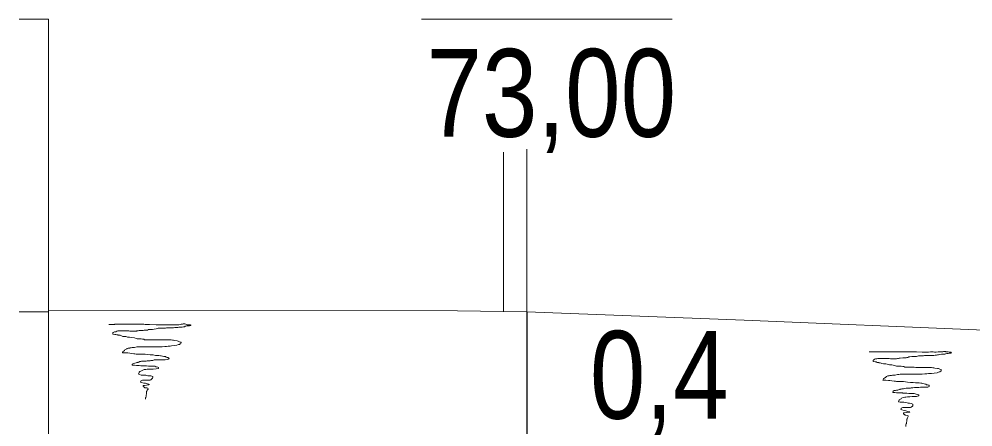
# Model space of a CAD drawing. Extents: x 640104 to 640970, y 6442278 to 6442689.
# Drawn here: x 640552.71 to 640585.31, y 6442645.01 to 6442658.94 of the extents above; entities that cross this region are included whole.
import ezdxf
from ezdxf.enums import TextEntityAlignment as Align

# ---------------------------------------------------------------- set-up
doc = ezdxf.new("R2010")
doc.units = 0
doc.header["$LTSCALE"] = 1.2
for name, color, linetype, lineweight in [('30', 7, 'Continuous', 13), ('31', 7, 'Continuous', 13), ('32', 7, 'Continuous', 25), ('35', 7, 'Continuous', 35), ('40', 7, 'Continuous', 13)]:
    doc.layers.add(name, color=color, linetype=linetype, lineweight=lineweight)

msp = doc.modelspace()

# ---------------------------------------------------------------- linework, layer by layer
at = {"layer": '30'}
for p, q in [((640552.71, 6442658.94), (640553.71, 6442658.94)), ((640553.71, 6442488.94), (640553.71, 6442658.94)), ((640552.71, 6442648.94), (640553.71, 6442648.94))]:
    msp.add_line(p, q, dxfattribs=at)
at = {"layer": '31'}
msp.add_lwpolyline([(640553.71, 6442649), (640567.7, 6442648.97), (640570.07, 6442648.94), (640577.49, 6442648.66), (640585.71, 6442648.31), (640594.63, 6442647.18), (640602.39, 6442645.28), (640608.86, 6442643.53), (640614.97, 6442642.09), (640621.18, 6442640.93)], dxfattribs=at)
at = {"layer": '32', "lineweight": 13}
msp.add_line((640566.46, 6442658.94), (640575.03, 6442658.94), dxfattribs=at)
at = {"layer": '32'}
msp.add_line((640570.07, 6442648.94), (640570.07, 6442558.94), dxfattribs=at)
at = {"layer": '35', "lineweight": 13}
for p, q in [((640569.27, 6442648.94), (640569.27, 6442654.4)), ((640570.07, 6442648.94), (640570.07, 6442654.5))]:
    msp.add_line(p, q, dxfattribs=at)
at = {"layer": '40'}
for points in [[(640555.78, 6442648.51), (640555.82, 6442648.51), (640555.89, 6442648.51), (640555.97, 6442648.51), (640555.98, 6442648.52), (640556.05, 6442648.52), (640556.16, 6442648.52), (640556.37, 6442648.52), (640556.49, 6442648.52), (640556.52, 6442648.52), (640556.54, 6442648.52), (640556.59, 6442648.52), (640556.65, 6442648.52), (640556.72, 6442648.52), (640556.77, 6442648.52), (640556.81, 6442648.52), (640556.87, 6442648.52), (640556.92, 6442648.52), (640556.97, 6442648.52), (640557.02, 6442648.51), (640557.05, 6442648.51), (640557.1, 6442648.51), (640557.17, 6442648.51), (640557.39, 6442648.5), (640557.6, 6442648.5), (640557.66, 6442648.5), (640557.7, 6442648.5), (640557.73, 6442648.5), (640557.76, 6442648.5), (640557.81, 6442648.5), (640557.87, 6442648.5), (640557.9, 6442648.5), (640557.93, 6442648.5), (640557.94, 6442648.5), (640557.97, 6442648.5), (640558.01, 6442648.5), (640558.04, 6442648.5), (640558.07, 6442648.5), (640558.13, 6442648.5), (640558.17, 6442648.5), (640558.22, 6442648.51), (640558.25, 6442648.52), (640558.29, 6442648.52), (640558.32, 6442648.53), (640558.35, 6442648.53), (640558.38, 6442648.53), (640558.41, 6442648.52), (640558.43, 6442648.51), (640558.46, 6442648.5), (640558.49, 6442648.5)], [(640558.49, 6442648.5), (640558.52, 6442648.5), (640558.54, 6442648.5), (640558.57, 6442648.5), (640558.59, 6442648.48), (640558.57, 6442648.47), (640558.58, 6442648.48), (640558.56, 6442648.47), (640558.53, 6442648.46), (640558.49, 6442648.46), (640558.46, 6442648.46), (640558.43, 6442648.46), (640558.41, 6442648.45), (640558.38, 6442648.45), (640558.37, 6442648.43), (640558.33, 6442648.43), (640558.28, 6442648.42), (640558.25, 6442648.42), (640558.17, 6442648.42), (640558.14, 6442648.41), (640558.12, 6442648.41), (640558.09, 6442648.4), (640558.05, 6442648.4), (640558.03, 6442648.4), (640557.99, 6442648.39), (640557.97, 6442648.39), (640557.89, 6442648.39), (640557.85, 6442648.39), (640557.81, 6442648.39), (640557.75, 6442648.39), (640557.71, 6442648.38), (640557.68, 6442648.38), (640557.64, 6442648.38), (640557.6, 6442648.38), (640557.49, 6442648.38), (640557.46, 6442648.38), (640557.44, 6442648.37), (640557.39, 6442648.36), (640557.33, 6442648.35), (640557.27, 6442648.34), (640557.23, 6442648.34), (640557.17, 6442648.34), (640557.13, 6442648.34), (640557.1, 6442648.32), (640557.06, 6442648.32), (640557.05, 6442648.31), (640557.02, 6442648.31), (640556.98, 6442648.31), (640556.95, 6442648.3), (640556.93, 6442648.3), (640556.84, 6442648.3), (640556.81, 6442648.3)], [(640556.81, 6442648.3), (640556.78, 6442648.29), (640556.74, 6442648.29), (640556.72, 6442648.28), (640556.69, 6442648.28), (640556.67, 6442648.28), (640556.64, 6442648.28), (640556.61, 6442648.28), (640556.57, 6442648.28), (640556.53, 6442648.28), (640556.5, 6442648.28), (640556.46, 6442648.29), (640556.44, 6442648.29), (640556.41, 6442648.29), (640556.39, 6442648.29), (640556.36, 6442648.29), (640556.33, 6442648.29), (640556.28, 6442648.29), (640556.25, 6442648.29), (640556.23, 6442648.29), (640556.19, 6442648.29), (640556.17, 6442648.29), (640556.13, 6442648.29), (640556.11, 6442648.29), (640556.08, 6442648.29), (640556.05, 6442648.28), (640556.02, 6442648.26), (640555.99, 6442648.26), (640555.97, 6442648.26), (640555.95, 6442648.25), (640555.93, 6442648.24), (640555.92, 6442648.22), (640555.91, 6442648.2), (640555.92, 6442648.18), (640555.98, 6442648.17), (640556.02, 6442648.17), (640556.05, 6442648.15), (640556.08, 6442648.15), (640556.1, 6442648.14), (640556.12, 6442648.14), (640556.16, 6442648.14), (640556.19, 6442648.13), (640556.21, 6442648.12), (640556.26, 6442648.1), (640556.31, 6442648.1), (640556.36, 6442648.1), (640556.39, 6442648.09), (640556.42, 6442648.08), (640556.48, 6442648.07), (640556.55, 6442648.06)], [(640556.55, 6442648.06), (640556.65, 6442648.05), (640556.71, 6442648.03), (640556.75, 6442648.02), (640556.81, 6442648.02), (640556.88, 6442648.02), (640556.93, 6442648.01), (640556.97, 6442648.01), (640557, 6442647.99), (640557.05, 6442647.99), (640557.09, 6442647.99), (640557.15, 6442647.98), (640557.21, 6442647.98), (640557.25, 6442647.98), (640557.32, 6442647.98), (640557.37, 6442647.98), (640557.41, 6442647.98), (640557.44, 6442647.98), (640557.49, 6442647.98), (640557.53, 6442647.98), (640557.59, 6442647.98), (640557.65, 6442647.98), (640557.71, 6442647.98), (640557.75, 6442647.98), (640557.81, 6442647.98), (640557.83, 6442647.98), (640557.87, 6442647.98), (640557.91, 6442647.98), (640557.95, 6442647.97), (640557.99, 6442647.97), (640558.02, 6442647.96), (640558.11, 6442647.95), (640558.15, 6442647.94), (640558.19, 6442647.92), (640558.22, 6442647.91), (640558.25, 6442647.9), (640558.25, 6442647.88), (640558.24, 6442647.86), (640558.22, 6442647.85), (640558.21, 6442647.84), (640558.19, 6442647.82), (640558.16, 6442647.82), (640558.1, 6442647.8), (640558.01, 6442647.79), (640557.92, 6442647.78), (640557.87, 6442647.77), (640557.81, 6442647.77), (640557.75, 6442647.76), (640557.69, 6442647.76), (640557.6, 6442647.75), (640557.47, 6442647.75), (640557.36, 6442647.75)], [(640557.36, 6442647.75), (640557.3, 6442647.75), (640557.25, 6442647.75), (640557.2, 6442647.75), (640557.16, 6442647.75), (640557.12, 6442647.75), (640557.06, 6442647.75), (640557.01, 6442647.74), (640556.89, 6442647.74), (640556.83, 6442647.74), (640556.8, 6442647.74), (640556.74, 6442647.74), (640556.66, 6442647.72), (640556.57, 6442647.72), (640556.54, 6442647.71), (640556.5, 6442647.71), (640556.49, 6442647.7), (640556.46, 6442647.7), (640556.44, 6442647.7), (640556.41, 6442647.69), (640556.39, 6442647.68), (640556.37, 6442647.66), (640556.33, 6442647.64), (640556.31, 6442647.62), (640556.3, 6442647.61), (640556.28, 6442647.6), (640556.27, 6442647.58), (640556.25, 6442647.57), (640556.25, 6442647.55), (640556.26, 6442647.54), (640556.29, 6442647.54), (640556.33, 6442647.54), (640556.36, 6442647.54), (640556.43, 6442647.54), (640556.49, 6442647.53), (640556.55, 6442647.52), (640556.63, 6442647.51), (640556.67, 6442647.51), (640556.71, 6442647.5), (640556.75, 6442647.5), (640556.86, 6442647.5), (640556.95, 6442647.5), (640557.02, 6442647.49), (640557.09, 6442647.48), (640557.19, 6442647.47), (640557.29, 6442647.47), (640557.37, 6442647.45), (640557.42, 6442647.45), (640557.49, 6442647.45), (640557.54, 6442647.44)], [(640557.54, 6442647.44), (640557.57, 6442647.44), (640557.61, 6442647.43), (640557.66, 6442647.42), (640557.71, 6442647.41), (640557.74, 6442647.39), (640557.77, 6442647.38), (640557.81, 6442647.38), (640557.83, 6442647.37), (640557.84, 6442647.34), (640557.82, 6442647.33), (640557.81, 6442647.32), (640557.78, 6442647.31), (640557.7, 6442647.3), (640557.66, 6442647.3), (640557.64, 6442647.3), (640557.59, 6442647.3), (640557.53, 6442647.3), (640557.48, 6442647.3), (640557.45, 6442647.3), (640557.41, 6442647.3), (640557.33, 6442647.3), (640557.28, 6442647.28), (640557.25, 6442647.28), (640557.21, 6442647.28), (640557.19, 6442647.27), (640557.15, 6442647.27), (640557.09, 6442647.27), (640557.05, 6442647.26), (640556.99, 6442647.26), (640556.95, 6442647.25), (640556.93, 6442647.25), (640556.89, 6442647.25), (640556.87, 6442647.24), (640556.83, 6442647.24), (640556.82, 6442647.22), (640556.78, 6442647.22), (640556.77, 6442647.21), (640556.74, 6442647.21), (640556.71, 6442647.2), (640556.67, 6442647.19), (640556.63, 6442647.18), (640556.6, 6442647.17), (640556.58, 6442647.15), (640556.58, 6442647.12), (640556.61, 6442647.12), (640556.65, 6442647.12), (640556.72, 6442647.11), (640556.77, 6442647.11), (640556.81, 6442647.11), (640556.87, 6442647.1), (640556.91, 6442647.1)], [(640581.77, 6442647.57), (640581.81, 6442647.57), (640581.88, 6442647.57), (640581.95, 6442647.57), (640581.97, 6442647.58), (640582.04, 6442647.58), (640582.14, 6442647.58), (640582.36, 6442647.58), (640582.48, 6442647.58), (640582.5, 6442647.58), (640582.53, 6442647.58), (640582.58, 6442647.58), (640582.63, 6442647.58), (640582.7, 6442647.58), (640582.76, 6442647.58), (640582.8, 6442647.58), (640582.86, 6442647.58), (640582.9, 6442647.58), (640582.95, 6442647.58), (640583.01, 6442647.57), (640583.04, 6442647.57), (640583.09, 6442647.57), (640583.15, 6442647.57), (640583.38, 6442647.57), (640583.58, 6442647.56), (640583.65, 6442647.56), (640583.69, 6442647.56), (640583.71, 6442647.56), (640583.74, 6442647.56), (640583.79, 6442647.56), (640583.86, 6442647.57), (640583.89, 6442647.57), (640583.91, 6442647.57), (640583.93, 6442647.57), (640583.95, 6442647.57), (640584, 6442647.56), (640584.02, 6442647.56), (640584.06, 6442647.56), (640584.12, 6442647.57), (640584.16, 6442647.57), (640584.21, 6442647.57), (640584.23, 6442647.58), (640584.28, 6442647.58), (640584.3, 6442647.59), (640584.34, 6442647.59), (640584.37, 6442647.59), (640584.39, 6442647.58), (640584.42, 6442647.57), (640584.45, 6442647.57), (640584.47, 6442647.57)], [(640584.47, 6442647.57), (640584.5, 6442647.56), (640584.53, 6442647.56), (640584.56, 6442647.56), (640584.58, 6442647.54), (640584.56, 6442647.53), (640584.57, 6442647.54), (640584.54, 6442647.53), (640584.51, 6442647.53), (640584.47, 6442647.52), (640584.45, 6442647.52), (640584.42, 6442647.52), (640584.39, 6442647.51), (640584.37, 6442647.51), (640584.35, 6442647.49), (640584.31, 6442647.49), (640584.26, 6442647.49), (640584.24, 6442647.49), (640584.16, 6442647.48), (640584.13, 6442647.47), (640584.1, 6442647.47), (640584.07, 6442647.46), (640584.04, 6442647.46), (640584.02, 6442647.46), (640583.98, 6442647.45), (640583.95, 6442647.45), (640583.88, 6442647.45), (640583.84, 6442647.45), (640583.79, 6442647.45), (640583.74, 6442647.45), (640583.7, 6442647.45), (640583.66, 6442647.45), (640583.62, 6442647.44), (640583.58, 6442647.44), (640583.47, 6442647.44), (640583.45, 6442647.44), (640583.42, 6442647.43), (640583.38, 6442647.42), (640583.31, 6442647.41), (640583.26, 6442647.41), (640583.22, 6442647.41), (640583.16, 6442647.4), (640583.12, 6442647.4), (640583.09, 6442647.38), (640583.05, 6442647.38), (640583.03, 6442647.37), (640583.01, 6442647.37), (640582.97, 6442647.37), (640582.94, 6442647.37), (640582.91, 6442647.37), (640582.82, 6442647.36), (640582.79, 6442647.36)], [(640582.79, 6442647.36), (640582.77, 6442647.35), (640582.73, 6442647.35), (640582.7, 6442647.34), (640582.68, 6442647.34), (640582.66, 6442647.34), (640582.62, 6442647.34), (640582.59, 6442647.34), (640582.56, 6442647.34), (640582.51, 6442647.34), (640582.49, 6442647.34), (640582.45, 6442647.35), (640582.42, 6442647.35), (640582.4, 6442647.35), (640582.38, 6442647.35), (640582.34, 6442647.35), (640582.31, 6442647.35), (640582.26, 6442647.35), (640582.24, 6442647.35), (640582.22, 6442647.35), (640582.18, 6442647.35), (640582.15, 6442647.35), (640582.12, 6442647.35), (640582.1, 6442647.35), (640582.06, 6442647.35), (640582.03, 6442647.34), (640582.01, 6442647.33), (640581.98, 6442647.33), (640581.95, 6442647.32), (640581.94, 6442647.31), (640581.92, 6442647.3), (640581.9, 6442647.29), (640581.9, 6442647.26), (640581.9, 6442647.24), (640581.97, 6442647.23), (640582.01, 6442647.23), (640582.03, 6442647.21), (640582.06, 6442647.21), (640582.09, 6442647.21), (640582.1, 6442647.2), (640582.14, 6442647.2), (640582.18, 6442647.19), (640582.2, 6442647.18), (640582.25, 6442647.17), (640582.3, 6442647.16), (640582.34, 6442647.16), (640582.38, 6442647.15), (640582.41, 6442647.14), (640582.46, 6442647.13), (640582.54, 6442647.13)], [(640582.54, 6442647.13), (640582.63, 6442647.11), (640582.7, 6442647.09), (640582.74, 6442647.09), (640582.8, 6442647.08), (640582.86, 6442647.08), (640582.91, 6442647.07), (640582.95, 6442647.07), (640582.98, 6442647.05), (640583.04, 6442647.05), (640583.08, 6442647.05), (640583.14, 6442647.05), (640583.19, 6442647.05), (640583.24, 6442647.05), (640583.3, 6442647.05), (640583.36, 6442647.04), (640583.4, 6442647.04), (640583.42, 6442647.04), (640583.47, 6442647.04), (640583.52, 6442647.04), (640583.58, 6442647.04), (640583.64, 6442647.04), (640583.7, 6442647.04), (640583.74, 6442647.04), (640583.79, 6442647.04), (640583.82, 6442647.04), (640583.86, 6442647.04), (640583.9, 6442647.04), (640583.94, 6442647.03), (640583.98, 6442647.03), (640584.01, 6442647.02), (640584.1, 6442647.01), (640584.14, 6442647), (640584.18, 6442646.98), (640584.21, 6442646.97), (640584.23, 6442646.97), (640584.23, 6442646.94), (640584.22, 6442646.92), (640584.21, 6442646.91), (640584.19, 6442646.9), (640584.18, 6442646.89), (640584.14, 6442646.88), (640584.09, 6442646.86), (640583.99, 6442646.85), (640583.9, 6442646.84), (640583.86, 6442646.83), (640583.79, 6442646.83), (640583.74, 6442646.82), (640583.67, 6442646.82), (640583.58, 6442646.81), (640583.46, 6442646.81), (640583.34, 6442646.81)], [(640556.91, 6442647.1), (640556.93, 6442647.1), (640556.95, 6442647.1), (640556.99, 6442647.1), (640557.04, 6442647.1), (640557.06, 6442647.1), (640557.13, 6442647.09), (640557.19, 6442647.09), (640557.21, 6442647.09), (640557.25, 6442647.09), (640557.27, 6442647.09), (640557.31, 6442647.09), (640557.35, 6442647.08), (640557.38, 6442647.06), (640557.41, 6442647.06), (640557.45, 6442647.05), (640557.47, 6442647.04), (640557.47, 6442647.01), (640557.39, 6442646.99), (640557.29, 6442646.98), (640557.25, 6442646.98), (640557.17, 6442646.98), (640557.13, 6442646.98), (640557.09, 6442646.98), (640557.04, 6442646.97), (640556.99, 6442646.97), (640556.94, 6442646.95), (640556.89, 6442646.93), (640556.87, 6442646.91), (640556.84, 6442646.9), (640556.82, 6442646.88), (640556.81, 6442646.86), (640556.8, 6442646.84), (640556.78, 6442646.82), (640556.8, 6442646.81), (640556.83, 6442646.8), (640556.88, 6442646.78), (640556.97, 6442646.78), (640557.04, 6442646.78), (640557.08, 6442646.77), (640557.11, 6442646.76), (640557.16, 6442646.76), (640557.21, 6442646.75), (640557.28, 6442646.73), (640557.28, 6442646.7), (640557.27, 6442646.67), (640557.26, 6442646.66), (640557.21, 6442646.62), (640557.19, 6442646.61), (640557.15, 6442646.61), (640557.09, 6442646.61), (640557.04, 6442646.61), (640556.99, 6442646.61), (640556.93, 6442646.61), (640556.88, 6442646.59), (640556.87, 6442646.57), (640556.86, 6442646.55), (640556.87, 6442646.54), (640556.89, 6442646.53), (640556.97, 6442646.5), (640557.03, 6442646.5), (640557.06, 6442646.49), (640557.1, 6442646.48), (640557.14, 6442646.47), (640557.17, 6442646.46), (640557.15, 6442646.45), (640557.11, 6442646.45), (640557.06, 6442646.44), (640557, 6442646.43), (640556.97, 6442646.43), (640556.95, 6442646.42), (640556.95, 6442646.39), (640556.97, 6442646.38), (640556.98, 6442646.37), (640557.01, 6442646.35), (640557.04, 6442646.34), (640557.08, 6442646.34), (640557.11, 6442646.33), (640557.12, 6442646.3), (640557.1, 6442646.28), (640557.09, 6442646.26), (640557.08, 6442646.23), (640557.06, 6442646.22), (640557.06, 6442646.18), (640557.06, 6442646.15), (640557.06, 6442646.13), (640557.05, 6442646.1), (640557.05, 6442646.07), (640557.05, 6442646.06), (640557.04, 6442646.02), (640557.03, 6442646), (640557.03, 6442645.97), (640557.03, 6442645.96), (640557.03, 6442645.98)], [(640583.34, 6442646.81), (640583.29, 6442646.81), (640583.24, 6442646.81), (640583.18, 6442646.81), (640583.14, 6442646.81), (640583.1, 6442646.81), (640583.05, 6442646.81), (640582.99, 6442646.81), (640582.87, 6442646.81), (640582.82, 6442646.81), (640582.78, 6442646.8), (640582.73, 6442646.8), (640582.65, 6442646.78), (640582.56, 6442646.78), (640582.53, 6442646.77), (640582.49, 6442646.77), (640582.47, 6442646.77), (640582.45, 6442646.76), (640582.42, 6442646.76), (640582.4, 6442646.75), (640582.38, 6442646.74), (640582.36, 6442646.73), (640582.32, 6442646.7), (640582.3, 6442646.69), (640582.29, 6442646.67), (640582.26, 6442646.66), (640582.26, 6442646.65), (640582.24, 6442646.63), (640582.23, 6442646.61), (640582.25, 6442646.61), (640582.27, 6442646.61), (640582.31, 6442646.61), (640582.34, 6442646.61), (640582.42, 6442646.6), (640582.47, 6442646.59), (640582.54, 6442646.58), (640582.62, 6442646.57), (640582.66, 6442646.57), (640582.7, 6442646.56), (640582.74, 6442646.56), (640582.85, 6442646.56), (640582.94, 6442646.56), (640583.01, 6442646.55), (640583.08, 6442646.54), (640583.18, 6442646.53), (640583.27, 6442646.53), (640583.35, 6442646.51), (640583.41, 6442646.51), (640583.47, 6442646.51), (640583.53, 6442646.5)], [(640583.53, 6442646.5), (640583.56, 6442646.5), (640583.59, 6442646.49), (640583.65, 6442646.48), (640583.7, 6442646.47), (640583.73, 6442646.45), (640583.76, 6442646.45), (640583.8, 6442646.44), (640583.82, 6442646.43), (640583.82, 6442646.4), (640583.81, 6442646.39), (640583.79, 6442646.38), (640583.77, 6442646.37), (640583.69, 6442646.37), (640583.65, 6442646.37), (640583.62, 6442646.37), (640583.58, 6442646.37), (640583.52, 6442646.37), (640583.46, 6442646.36), (640583.43, 6442646.36), (640583.4, 6442646.36), (640583.31, 6442646.36), (640583.26, 6442646.34), (640583.24, 6442646.34), (640583.2, 6442646.34), (640583.18, 6442646.33), (640583.14, 6442646.33), (640583.08, 6442646.33), (640583.03, 6442646.33), (640582.98, 6442646.32), (640582.94, 6442646.31), (640582.91, 6442646.31), (640582.88, 6442646.31), (640582.86, 6442646.3), (640582.82, 6442646.3), (640582.81, 6442646.29), (640582.77, 6442646.28), (640582.75, 6442646.27), (640582.73, 6442646.27), (640582.7, 6442646.26), (640582.66, 6442646.25), (640582.62, 6442646.25), (640582.58, 6442646.23), (640582.57, 6442646.21), (640582.57, 6442646.18), (640582.59, 6442646.18), (640582.64, 6442646.18), (640582.7, 6442646.17), (640582.76, 6442646.17), (640582.79, 6442646.17), (640582.86, 6442646.17), (640582.9, 6442646.17)], [(640582.9, 6442646.17), (640582.91, 6442646.16), (640582.94, 6442646.16), (640582.98, 6442646.16), (640583.02, 6442646.16), (640583.05, 6442646.16), (640583.12, 6442646.15), (640583.18, 6442646.15), (640583.2, 6442646.15), (640583.23, 6442646.15), (640583.26, 6442646.15), (640583.3, 6442646.15), (640583.34, 6442646.14), (640583.37, 6442646.13), (640583.4, 6442646.12), (640583.43, 6442646.11), (640583.46, 6442646.1), (640583.46, 6442646.07), (640583.38, 6442646.05), (640583.27, 6442646.05), (640583.23, 6442646.05), (640583.16, 6442646.04), (640583.12, 6442646.04), (640583.07, 6442646.04), (640583.02, 6442646.03), (640582.98, 6442646.03), (640582.93, 6442646.01), (640582.87, 6442645.99), (640582.86, 6442645.97), (640582.82, 6442645.96), (640582.81, 6442645.94), (640582.79, 6442645.93), (640582.78, 6442645.9), (640582.77, 6442645.88), (640582.78, 6442645.87), (640582.82, 6442645.86), (640582.86, 6442645.85), (640582.95, 6442645.85), (640583.02, 6442645.84), (640583.06, 6442645.83), (640583.1, 6442645.82), (640583.14, 6442645.82), (640583.2, 6442645.81), (640583.26, 6442645.79), (640583.26, 6442645.76), (640583.26, 6442645.73), (640583.25, 6442645.72), (640583.2, 6442645.68), (640583.18, 6442645.67), (640583.14, 6442645.67), (640583.08, 6442645.67), (640583.02, 6442645.67), (640582.98, 6442645.67), (640582.92, 6442645.67), (640582.86, 6442645.65), (640582.86, 6442645.63), (640582.85, 6442645.61), (640582.86, 6442645.6), (640582.88, 6442645.59), (640582.96, 6442645.57), (640583.02, 6442645.56), (640583.05, 6442645.55), (640583.09, 6442645.54), (640583.13, 6442645.53), (640583.15, 6442645.52), (640583.14, 6442645.51), (640583.1, 6442645.51), (640583.05, 6442645.5), (640582.98, 6442645.49), (640582.96, 6442645.49), (640582.94, 6442645.49), (640582.94, 6442645.45), (640582.95, 6442645.44), (640582.97, 6442645.43), (640582.99, 6442645.41), (640583.02, 6442645.41), (640583.06, 6442645.4), (640583.1, 6442645.39), (640583.1, 6442645.36), (640583.09, 6442645.34), (640583.08, 6442645.32), (640583.06, 6442645.29), (640583.05, 6442645.28), (640583.05, 6442645.25), (640583.05, 6442645.21), (640583.05, 6442645.19), (640583.04, 6442645.17), (640583.04, 6442645.13), (640583.03, 6442645.12), (640583.02, 6442645.09), (640583.02, 6442645.06), (640583.02, 6442645.03), (640583.02, 6442645.02), (640583.02, 6442645.05)]]:
    msp.add_lwpolyline(points, dxfattribs=at)

# ---------------------------------------------------------------- texts
at = {"layer": '32', "width": 0.85}
for s, p in [('73,00', (640570.9, 6442654.92)), ('0,4', (640574.59, 6442645.29))]:
    msp.add_text(s, height=3, dxfattribs=at).set_placement(p, align=Align.CENTER)

doc.saveas('drawing.dxf')
